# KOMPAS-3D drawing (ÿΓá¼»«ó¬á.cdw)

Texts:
  Задание Ш0
  Колесо зубчатое (штамповка)
  Noncommercial version
  Метод получения исходной заготовки - штамповка на
  Кривошипном горячештамповочном прессе
  Степень сложности по ГОСТ7505-89 - С1
  Группа стали по ГОСТ 7505-89 - М2
  4. Термообработка - улучшение
  5. НВ 350
  6. Неуказанные штамповочные уклоны 5
  7. Неуказанные радиусы закруглений 3
  8. Допускаемое смещение по поверхности разьема штампа 0,7мм
  9. Допускается величина высоты заусенца 5мм
  10. Точность изготовляемой исходной заготовки по  IT14
  11. Метод очистки от окалины - травление
  Rz80
  Колесо зубчатое
  (штамповка)
  Ходырев А.А.
  Тищенко Э.Э.
  Сталь 40ХН ГОСТ 4543-71
  ДГТУ
  Курсовая работа по ТМ-
Dimensions and other numbers on the sheet: 75,5; 1,75; 63,5; 53,5; 1,74; 5; 46; 181,5; 211; 2; 3; 17,6; 26,75; 1:1; 1; 11,5; 0; 4; 6; 7; 8; 9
